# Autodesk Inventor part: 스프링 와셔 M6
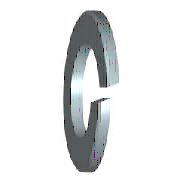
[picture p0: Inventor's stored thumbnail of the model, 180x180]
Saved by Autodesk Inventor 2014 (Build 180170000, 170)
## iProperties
IsCustomPart: 1
Created: 2012-02
Part Number: 스프링 와셔 M6
Material: 강철, 연강
Description: 스프링 와셔
Document SubType Name: Modeling
Standard: JIS B 1251
Designer: mdu-01
Standards Organization: JIS
Language: ko-KR
Size Designation: 번호 2 6
Categories: <MemberInstance><Categories><Category DisplayName="조임쇠" InternalName="e4da775c-781d-43d5-af7c-5136215cf5a6" Mnemonic="FSTN"><Category DisplayName="와셔" InternalN
Density: 7.86 g/cm^3
Mass: 1.01202 g
Surface Area: 2.65887 cm^2
Volume: 0.128756 cm^3
Appearance: 강철
Author: mdu-01
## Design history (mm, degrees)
sketch "스케치1"
  geometry: C1 r 6.1 at (0, 0); C2 r 3.05 at (0, 0); 1 further point
  constraints: 2 centre point, 2 coincident
  dimensions: "d0" = 6.1 diameter of C2 (= SD1); "d1" = 12.2 diameter of C1 (= SD2)
extrude "본체" new body sketch "스케치1" distance "d2" = 1.5 (= SD); taper "d3" = 0 deg
sketch "스케치2"
  geometry: L1 (0, -3.05)-(0, 3.05) reference; L2 (1.5, 6.1)-(1.5, -6.1) reference; L3 (-1.2, 0)-(7.2, 0) reference; L4 (0, -0.3)-(1.5, 0.246); L5 (0, 0.3)-(1.5, 0.846)
  constraints: 4 end point, 4 point on line, 1 parallel
  dimensions: "d4" = 0.3 distance from line of L3 L4.start (= 0.2 x SD); "d5" = 0.3 distance from line of L3 L5.start (= 0.2 x SD); "d6" = 70 deg angle of L2 L4 (= FAWI)
extrude "절단부" cut sketch "스케치2" stored distance "d7" = 1.5 (= SD); taper "d8" = 0 deg
workaxis "Work Axis1"
workplane "Work Plane1"
body "Solid1"
other parameters: "SD1" = 6.1 [user parameter; used in 1 equation term], "SD2" = 12.2 [user parameter; used in 1 equation term], "SD" = 1.5 [user parameter; used in 4 equation terms], "FAWI" = 70 deg [user parameter; used in 1 equation term], "d9" = 0, "d10" = 0, "d11" = 0, "d12" = 0, "SDI" = 2.7 [user parameter], "NND" = 6 [user parameter]
